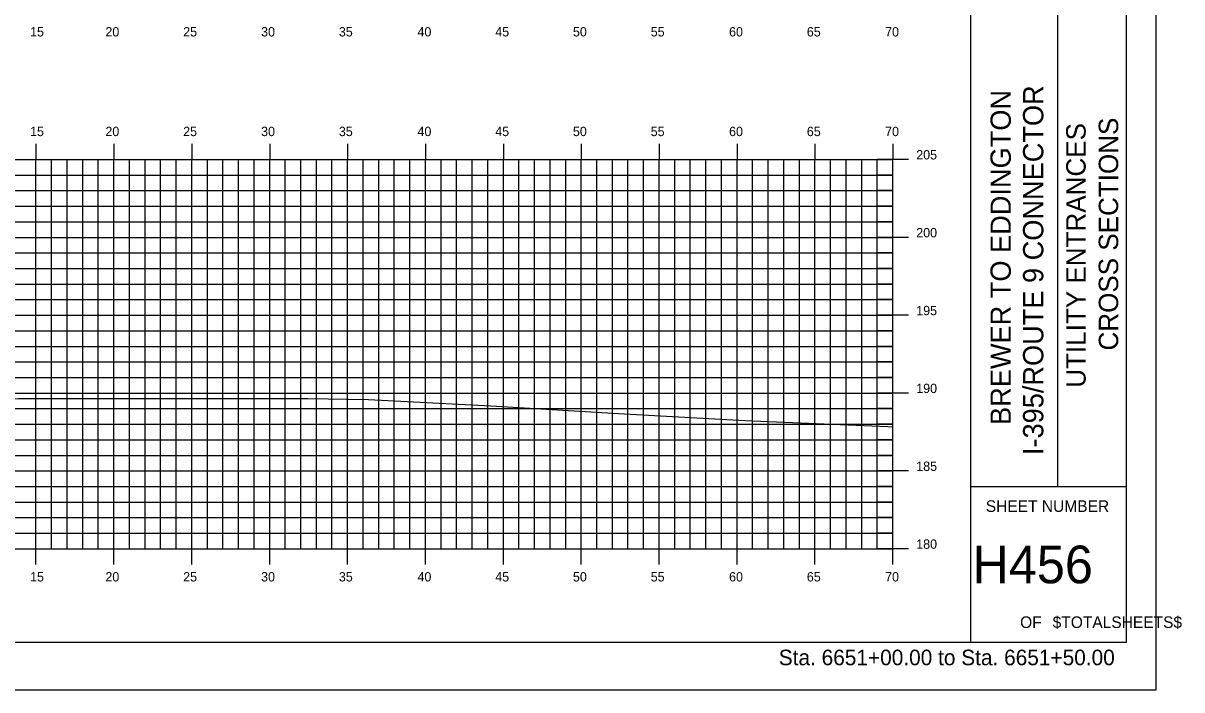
# Model space of a CAD drawing. Extents: x 1723543 to 1723714, y 458501 to 458611.
# Drawn here: x 1723640 to 1723714.3, y 458501.2 to 458544 of the extents above; entities that cross this region are included whole.
import ezdxf

# ---------------------------------------------------------------- set-up
doc = ezdxf.new("R2010")
doc.units = 0
for name, color, linetype in [('BORDER', 7, 'Continuous'), ('H_V ANNOTATION', 7, 'Continuous'), ('HIGHWAY_TITLE', 7, 'Continuous'), ('MAJOR', 7, 'Continuous'), ('MINOR', 7, 'Continuous'), ('PLOT BOUNDARY', 7, 'Continuous'), ('S_Roadway_Centerline', 7, 'Continuous')]:
    doc.layers.add(name, color=color, linetype=linetype)

msp = doc.modelspace()

# ---------------------------------------------------------------- linework, layer by layer
at = {"layer": 'BORDER'}
for p, q in [((1723700.786, 458504.254), (1723700.786, 458609.254)), ((1723706.377, 458514.257), (1723706.377, 458549.257)), ((1723700.786, 458514.257), (1723710.786, 458514.257))]:
    msp.add_line(p, q, dxfattribs=at)
msp.add_lwpolyline([(1723550.786, 458504.254), (1723710.786, 458504.254), (1723710.786, 458609.254), (1723550.786, 458609.254)], close=True, dxfattribs=at)
at = {"layer": 'MAJOR'}
for p, q in [((1723640.785, 458536.256), (1723640.785, 458535.254)), ((1723645.785, 458536.256), (1723645.785, 458535.254)), ((1723650.785, 458536.256), (1723650.785, 458535.254)), ((1723655.785, 458536.256), (1723655.785, 458535.254)), ((1723660.785, 458536.256), (1723660.785, 458535.254)), ((1723665.785, 458536.256), (1723665.785, 458535.254)), ((1723670.785, 458536.256), (1723670.785, 458535.254)), ((1723675.785, 458536.256), (1723675.785, 458535.254)), ((1723680.785, 458536.256), (1723680.785, 458535.254)), ((1723685.785, 458536.256), (1723685.785, 458535.254)), ((1723690.785, 458536.256), (1723690.785, 458535.254)), ((1723695.785, 458536.256), (1723695.785, 458535.254)), ((1723555.785, 458535.254), (1723695.785, 458535.254)), ((1723555.785, 458535.254), (1723695.785, 458535.254)), ((1723640.785, 458510.254), (1723640.785, 458535.254)), ((1723645.785, 458510.254), (1723645.785, 458535.254)), ((1723650.785, 458510.254), (1723650.785, 458535.254)), ((1723655.785, 458510.254), (1723655.785, 458535.254)), ((1723660.785, 458510.254), (1723660.785, 458535.254)), ((1723665.785, 458510.254), (1723665.785, 458535.254)), ((1723670.785, 458510.254), (1723670.785, 458535.254)), ((1723675.785, 458510.254), (1723675.785, 458535.254)), ((1723680.785, 458510.254), (1723680.785, 458535.254)), ((1723685.785, 458510.254), (1723685.785, 458535.254)), ((1723690.785, 458510.254), (1723690.785, 458535.254)), ((1723696.787, 458535.254), (1723694.783, 458535.254)), ((1723695.785, 458510.254), (1723695.785, 458535.254)), ((1723695.785, 458510.254), (1723695.785, 458535.254)), ((1723555.785, 458530.254), (1723695.785, 458530.254)), ((1723696.787, 458530.254), (1723694.783, 458530.254)), ((1723555.785, 458525.254), (1723695.785, 458525.254)), ((1723696.787, 458525.254), (1723694.783, 458525.254)), ((1723555.785, 458520.254), (1723695.785, 458520.254)), ((1723696.787, 458520.254), (1723694.783, 458520.254)), ((1723555.785, 458515.254), (1723695.785, 458515.254)), ((1723696.787, 458515.254), (1723694.783, 458515.254)), ((1723555.785, 458510.254), (1723695.785, 458510.254)), ((1723555.785, 458510.254), (1723695.785, 458510.254)), ((1723640.785, 458509.252), (1723640.785, 458510.254)), ((1723645.785, 458509.252), (1723645.785, 458510.254)), ((1723650.785, 458509.252), (1723650.785, 458510.254)), ((1723655.785, 458509.252), (1723655.785, 458510.254)), ((1723660.785, 458509.252), (1723660.785, 458510.254)), ((1723665.785, 458509.252), (1723665.785, 458510.254)), ((1723670.785, 458509.252), (1723670.785, 458510.254)), ((1723675.785, 458509.252), (1723675.785, 458510.254)), ((1723680.785, 458509.252), (1723680.785, 458510.254)), ((1723685.785, 458509.252), (1723685.785, 458510.254)), ((1723690.785, 458509.252), (1723690.785, 458510.254)), ((1723696.787, 458510.254), (1723694.783, 458510.254)), ((1723695.785, 458509.252), (1723695.785, 458510.254))]:
    msp.add_line(p, q, dxfattribs=at)
at = {"layer": 'MINOR'}
for p, q in [((1723641.785, 458510.254), (1723641.785, 458535.254)), ((1723642.785, 458510.254), (1723642.785, 458535.254)), ((1723643.785, 458510.254), (1723643.785, 458535.254)), ((1723644.785, 458510.254), (1723644.785, 458535.254)), ((1723646.785, 458510.254), (1723646.785, 458535.254)), ((1723647.785, 458510.254), (1723647.785, 458535.254)), ((1723648.785, 458510.254), (1723648.785, 458535.254)), ((1723649.785, 458510.254), (1723649.785, 458535.254)), ((1723651.785, 458510.254), (1723651.785, 458535.254)), ((1723652.785, 458510.254), (1723652.785, 458535.254)), ((1723653.785, 458510.254), (1723653.785, 458535.254)), ((1723654.785, 458510.254), (1723654.785, 458535.254)), ((1723656.785, 458510.254), (1723656.785, 458535.254)), ((1723657.785, 458510.254), (1723657.785, 458535.254)), ((1723658.785, 458510.254), (1723658.785, 458535.254)), ((1723659.785, 458510.254), (1723659.785, 458535.254)), ((1723661.785, 458510.254), (1723661.785, 458535.254)), ((1723662.785, 458510.254), (1723662.785, 458535.254)), ((1723663.785, 458510.254), (1723663.785, 458535.254)), ((1723664.785, 458510.254), (1723664.785, 458535.254)), ((1723666.785, 458510.254), (1723666.785, 458535.254)), ((1723667.785, 458510.254), (1723667.785, 458535.254)), ((1723668.785, 458510.254), (1723668.785, 458535.254)), ((1723669.785, 458510.254), (1723669.785, 458535.254)), ((1723671.785, 458510.254), (1723671.785, 458535.254)), ((1723672.785, 458510.254), (1723672.785, 458535.254)), ((1723673.785, 458510.254), (1723673.785, 458535.254)), ((1723674.785, 458510.254), (1723674.785, 458535.254)), ((1723676.785, 458510.254), (1723676.785, 458535.254)), ((1723677.785, 458510.254), (1723677.785, 458535.254)), ((1723678.785, 458510.254), (1723678.785, 458535.254)), ((1723679.785, 458510.254), (1723679.785, 458535.254)), ((1723681.785, 458510.254), (1723681.785, 458535.254)), ((1723682.785, 458510.254), (1723682.785, 458535.254)), ((1723683.785, 458510.254), (1723683.785, 458535.254)), ((1723684.785, 458510.254), (1723684.785, 458535.254)), ((1723686.785, 458510.254), (1723686.785, 458535.254)), ((1723687.785, 458510.254), (1723687.785, 458535.254)), ((1723688.785, 458510.254), (1723688.785, 458535.254)), ((1723689.785, 458510.254), (1723689.785, 458535.254)), ((1723691.785, 458510.254), (1723691.785, 458535.254)), ((1723692.785, 458510.254), (1723692.785, 458535.254)), ((1723693.785, 458510.254), (1723693.785, 458535.254)), ((1723694.785, 458510.254), (1723694.785, 458535.254)), ((1723555.785, 458534.254), (1723695.785, 458534.254)), ((1723695.785, 458534.254), (1723694.783, 458534.254)), ((1723555.785, 458533.254), (1723695.785, 458533.254)), ((1723695.785, 458533.254), (1723694.783, 458533.254)), ((1723555.785, 458532.254), (1723695.785, 458532.254)), ((1723695.785, 458532.254), (1723694.783, 458532.254)), ((1723555.785, 458531.254), (1723695.785, 458531.254)), ((1723695.785, 458531.254), (1723694.783, 458531.254)), ((1723555.785, 458529.254), (1723695.785, 458529.254)), ((1723695.785, 458529.254), (1723694.783, 458529.254)), ((1723555.785, 458528.254), (1723695.785, 458528.254)), ((1723695.785, 458528.254), (1723694.783, 458528.254)), ((1723555.785, 458527.254), (1723695.785, 458527.254)), ((1723695.785, 458527.254), (1723694.783, 458527.254)), ((1723555.785, 458526.254), (1723695.785, 458526.254)), ((1723695.785, 458526.254), (1723694.783, 458526.254)), ((1723555.785, 458524.254), (1723695.785, 458524.254)), ((1723695.785, 458524.254), (1723694.783, 458524.254)), ((1723555.785, 458523.254), (1723695.785, 458523.254)), ((1723695.785, 458523.254), (1723694.783, 458523.254)), ((1723555.785, 458522.254), (1723695.785, 458522.254)), ((1723695.785, 458522.254), (1723694.783, 458522.254)), ((1723555.785, 458521.254), (1723695.785, 458521.254)), ((1723695.785, 458521.254), (1723694.783, 458521.254)), ((1723555.785, 458519.254), (1723695.785, 458519.254)), ((1723695.785, 458519.254), (1723694.783, 458519.254)), ((1723555.785, 458518.254), (1723695.785, 458518.254)), ((1723695.785, 458518.254), (1723694.783, 458518.254)), ((1723555.785, 458517.254), (1723695.785, 458517.254)), ((1723695.785, 458517.254), (1723694.783, 458517.254)), ((1723555.785, 458516.254), (1723695.785, 458516.254)), ((1723695.785, 458516.254), (1723694.783, 458516.254)), ((1723555.785, 458514.254), (1723695.785, 458514.254)), ((1723695.785, 458514.254), (1723694.783, 458514.254)), ((1723555.785, 458513.254), (1723695.785, 458513.254)), ((1723695.785, 458513.254), (1723694.783, 458513.254)), ((1723555.785, 458512.254), (1723695.785, 458512.254)), ((1723695.785, 458512.254), (1723694.783, 458512.254)), ((1723555.785, 458511.254), (1723695.785, 458511.254)), ((1723695.785, 458511.254), (1723694.783, 458511.254))]:
    msp.add_line(p, q, dxfattribs=at)
at = {"layer": 'PLOT BOUNDARY'}
msp.add_lwpolyline([(1723542.692, 458501.195), (1723712.692, 458501.195), (1723712.692, 458611.195), (1723542.692, 458611.195)], close=True, dxfattribs=at)
at = {"layer": 'S_Roadway_Centerline'}
msp.add_lwpolyline([(1723555.785, 458522.191), (1723564.001, 458522.199), (1723565.758, 458522.124), (1723569.789, 458521.964), (1723578.235, 458521.495), (1723582.205, 458521.436), (1723589.984, 458521.219), (1723602.381, 458521.12), (1723602.509, 458521.117), (1723602.82, 458521.11), (1723620.494, 458520.565), (1723626.006, 458520.489), (1723636.736, 458519.983), (1723638.614, 458519.89), (1723639.657, 458519.909), (1723642.964, 458519.912), (1723658.245, 458519.9), (1723662.139, 458519.842), (1723669.988, 458519.439), (1723678.17, 458518.931), (1723686.285, 458518.491), (1723695.453, 458518.097), (1723695.785, 458518.085)], dxfattribs=at)

# ---------------------------------------------------------------- texts
at = {"layer": 'BORDER'}
for s, p in [('CROSS SECTIONS', (1723710.25, 458522.988)), ('UTILITY ENTRANCES', (1723708.162, 458520.597))]:
    msp.add_text(s, height=1.25, rotation=90, dxfattribs=at).set_placement(p)
for s, height, p in [('SHEET NUMBER', 0.74527, (1723701.751, 458512.621)), ('H456', 2.4194, (1723700.891, 458508.037)), ('OF', 0.7453, (1723703.953, 458505.167)), ('$TOTALSHEETS$', 0.74527, (1723706.042, 458505.167))]:
    msp.add_text(s, height=height, dxfattribs=at).set_placement(p)
at = {"layer": 'H_V ANNOTATION'}
for s, height, p in [('15', 0.6, (1723640.403, 458543.154)), ('20', 0.6, (1723645.239, 458543.154)), ('25', 0.6, (1723650.231, 458543.154)), ('30', 0.6, (1723655.234, 458543.154)), ('35', 0.6, (1723660.226, 458543.154)), ('40', 0.6, (1723665.272, 458543.154)), ('45', 0.6, (1723670.264, 458543.154)), ('50', 0.6, (1723675.25, 458543.154)), ('55', 0.6, (1723680.242, 458543.154)), ('60', 0.6, (1723685.272, 458543.154)), ('65', 0.6, (1723690.264, 458543.154)), ('70', 0.6, (1723695.287, 458543.154)), ('15', 0.6, (1723640.403, 458536.754)), ('20', 0.6, (1723645.239, 458536.754)), ('25', 0.6, (1723650.231, 458536.754)), ('30', 0.6, (1723655.234, 458536.754)), ('35', 0.6, (1723660.226, 458536.754)), ('40', 0.6, (1723665.272, 458536.754)), ('45', 0.6, (1723670.264, 458536.754)), ('50', 0.6, (1723675.25, 458536.754)), ('55', 0.6, (1723680.242, 458536.754)), ('60', 0.6, (1723685.272, 458536.754)), ('65', 0.6, (1723690.264, 458536.754)), ('70', 0.6, (1723695.287, 458536.754)), ('205', 0.6, (1723697.285, 458535.254)), ('200', 0.6, (1723697.285, 458530.254)), ('195', 0.6, (1723697.285, 458525.254)), ('190', 0.6, (1723697.285, 458520.254)), ('185', 0.6, (1723697.285, 458515.254)), ('180', 0.6, (1723697.285, 458510.254)), ('15', 0.6, (1723640.403, 458508.154)), ('20', 0.6, (1723645.239, 458508.154)), ('25', 0.6, (1723650.231, 458508.154)), ('30', 0.6, (1723655.234, 458508.154)), ('35', 0.6, (1723660.226, 458508.154)), ('40', 0.6, (1723665.272, 458508.154)), ('45', 0.6, (1723670.264, 458508.154)), ('50', 0.6, (1723675.25, 458508.154)), ('55', 0.6, (1723680.242, 458508.154)), ('60', 0.6, (1723685.272, 458508.154)), ('65', 0.6, (1723690.264, 458508.154)), ('70', 0.6, (1723695.287, 458508.154)), ('Sta. 6651+00.00 to Sta. 6651+50.00', 1.0002, (1723688.462, 458502.774))]:
    msp.add_text(s, height=height, dxfattribs=at).set_placement(p)
at = {"layer": 'HIGHWAY_TITLE'}
for s, p in [('BREWER TO EDDINGTON', (1723703.358, 458518.206)), ('I-395/ROUTE 9 CONNECTOR', (1723705.445, 458516.273))]:
    msp.add_text(s, height=1.30428, rotation=90, dxfattribs=at).set_placement(p)

doc.saveas('drawing.dxf')
